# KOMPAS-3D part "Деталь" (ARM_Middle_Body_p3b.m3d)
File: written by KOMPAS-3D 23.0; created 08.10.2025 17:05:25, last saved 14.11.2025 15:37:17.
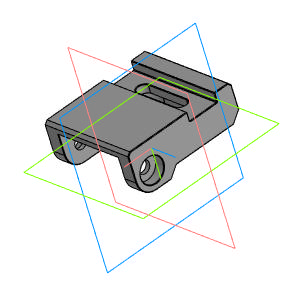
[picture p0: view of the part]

Document properties: Автор: ADMIN; Полное имя файла: D:\YandexDisk\Model\NVG\ARM mkII\ARM Middle Body p3b.m3d

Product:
- Part/product: Деталь
    Масса: 0.081974

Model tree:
1. Эскиз:1
2. Элемент выдавливания:1
     Расстояние 1 = 35
3. Эскиз:2  (with: Элемент выдавливания:1)
4. Элемент выдавливания:2
     Расстояние 2 = 12.2
5. Эскиз:3  (with: Элемент выдавливания:1)
6. Элемент выдавливания:3
     Расстояние 2 = 3
7. Эскиз:4  (with: Элемент выдавливания:1)
8. Элемент выдавливания:4
     Расстояние 2 = 35
9. Эскиз:5  (with: Элемент выдавливания:3)
10. Элемент выдавливания:5
11. Эскиз:6  (with: Элемент выдавливания:4, Элемент выдавливания:3)
12. Элемент выдавливания:6
     Расстояние 2 = 6
13. Эскиз:7  (with: Элемент выдавливания:1)
14. Элемент выдавливания:7
     Расстояние 2 = 3.5
15. Скругление:1  (with: Элемент выдавливания:1, Элемент выдавливания:2)
     Радиус = 5.5
16. Эскиз:8  (with: Элемент выдавливания:1)
17. Элемент выдавливания:8
     Расстояние 2 = 3.5
18. Эскиз:9  (with: Элемент выдавливания:1)
19. Элемент выдавливания:9
     Расстояние 2 = 0.5
20. Скругление:2  (with: Элемент выдавливания:5)
     Радиус = 2
21. Скругление:3  (with: Элемент выдавливания:6)
     Радиус = 5
22. Фаска:1  (with: Элемент выдавливания:4)
     Угол = 45; Длина 1 = 3; Длина 2 = 3
23. Фаска:2  (with: Фаска:1, Элемент выдавливания:1)
     Угол = 45; Длина 1 = 1; Длина 2 = 1
24. Фаска:3  (with: Элемент выдавливания:3, Фаска:1, Элемент выдавливания:1, Элемент выдавливания:6, Элемент выдавливания:2, Скругление:1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)
     Угол = 45; Длина 1 = 0.2; Длина 2 = 0.2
